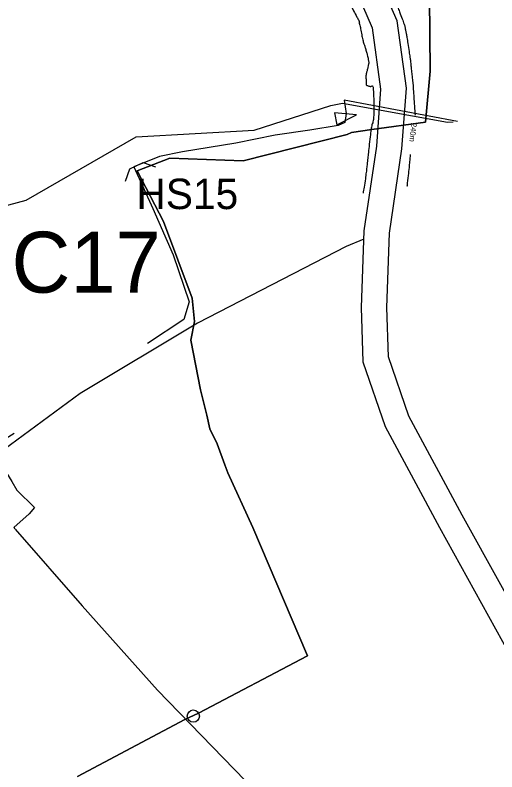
# Model space of a CAD drawing. Extents: x -478495 to -472450, y -1118050 to -1113745.
# Drawn here: x -476752.6 to -476594.3, y -1115728.8 to -1115480.3 of the extents above; entities that cross this region are included whole.
import ezdxf

# ---------------------------------------------------------------- set-up
doc = ezdxf.new("R2010")
doc.units = 0
for name, color, linetype in [('cesty', 7, 'Continuous'), ('el vedeni _VN', 7, 'Continuous'), ('el vedeni_NN', 7, 'Continuous'), ('hospodářské sjezdy', 7, 'Continuous'), ('ObPÚ', 7, 'Continuous'), ('vodní plochy', 7, 'Continuous'), ('Vrstevnice_hlavni', 7, 'Continuous'), ('Vrstevnice_popis', 7, 'Continuous')]:
    doc.layers.add(name, color=color, linetype=linetype)

msp = doc.modelspace()

# ---------------------------------------------------------------- linework, layer by layer
at = {"layer": 'cesty'}
msp.add_line((-476647.67265629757, -1115512.3904582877), (-476646.9333437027, -1115516.321541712), dxfattribs=at)
msp.add_lwpolyline([(-476646.9333437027, -1115516.321541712), (-476640.4761246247, -1115513.0720804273), (-476647.67265629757, -1115512.3904582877)], dxfattribs=at)
msp.add_circle((-476694.08534708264, -1115710.4661019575), 2, dxfattribs=at)
at = {"layer": 'el vedeni _VN'}
for points in [[(-476960.505, -1115493.233), (-476958.229, -1115494.183), (-476899.623, -1115513.536), (-476849.434, -1115530.972), (-476828.522, -1115538.992), (-476787.371, -1115551.3360000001), (-476749.039, -1115541.109), (-476712.836, -1115520.229), (-476674.07800000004, -1115518.099), (-476648.949, -1115510.002), (-476645.0645000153, -1115509.1674999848), (-476610.607, -1115515.4054999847), (-476608.699, -1115515.3360000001)], [(-476607.29025000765, -1115515.24), (-476644.57, -1115508.27), (-476643.83, -1115512.6285000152), (-476644.33, -1115515.5485000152), (-476646.46, -1115516.5485000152), (-476655.81, -1115518.0985000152), (-476667.18, -1115519.7085000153), (-476680.17, -1115522.3285000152), (-476697.65, -1115525.2285000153), (-476705.17, -1115526.7285000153), (-476713.65, -1115530.1385000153), (-476707.36, -1115543.8085000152), (-476700.72000000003, -1115559.0085000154), (-476695.5, -1115574.4385000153), (-476697.2, -1115580.2585000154), (-476709.1420331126, -1115588.1778778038)], [(-476752.99, -1115617.645), (-476760.59, -1115622.4385000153), (-476753.68, -1115633.3885000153), (-476752.07, -1115636.2785000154), (-476746.28, -1115641.9985000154), (-476748.07, -1115644.0885000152), (-476753.11, -1115648.49), (-476752.7125000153, -1115648.935)]]:
    msp.add_lwpolyline(points, dxfattribs=at)
at = {"layer": 'el vedeni_NN'}
msp.add_lwpolyline([(-476752.574, -1115649.0925000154), (-476730.57, -1115674.25), (-476705.81, -1115701.99), (-476648.0910886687, -1115761.4029674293)], dxfattribs=at)
at = {"layer": 'hospodářské sjezdy'}
for p, q in [((-476714.955, -1115530.759), (-476710.5445180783, -1115528.6585611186)), ((-476710.5445180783, -1115528.6585611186), (-476706.52371015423, -1115530.0823549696)), ((-476716.3837131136, -1115534.778062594), (-476714.955, -1115530.759))]:
    msp.add_line(p, q, dxfattribs=at)
at = {"layer": 'ObPÚ'}
for p, q in [((-476616.6289291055, -1115459.8410812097), (-476616.2596414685, -1115498.6901405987)), ((-476616.2596414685, -1115498.6901405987), (-476616.6289291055, -1115459.8410812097)), ((-476616.2596414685, -1115498.6901405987), (-476617.82961543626, -1115515.4656638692)), ((-476617.82961543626, -1115515.4656638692), (-476616.2596414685, -1115498.6901405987)), ((-476617.82961543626, -1115515.4656638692), (-476635.39030686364, -1115517.8817167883)), ((-476635.39030686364, -1115517.8817167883), (-476617.82961543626, -1115515.4656638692)), ((-476642.12939695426, -1115518.8089011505), (-476643.54326731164, -1115519.5005700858)), ((-476643.54326731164, -1115519.5005700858), (-476642.12939695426, -1115518.8089011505)), ((-476635.39030686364, -1115517.8817167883), (-476642.12939695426, -1115518.8089011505)), ((-476642.12939695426, -1115518.8089011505), (-476635.39030686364, -1115517.8817167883)), ((-476643.54326731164, -1115519.5005700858), (-476677.6648575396, -1115528.1907129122)), ((-476677.6648575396, -1115528.1907129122), (-476643.54326731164, -1115519.5005700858)), ((-476701.7930954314, -1115527.2491543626), (-476712.5505217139, -1115531.3951539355)), ((-476712.5505217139, -1115531.3951539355), (-476701.7930954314, -1115527.2491543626)), ((-476677.6648575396, -1115528.1907129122), (-476701.7930954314, -1115527.2491543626)), ((-476701.7930954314, -1115527.2491543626), (-476677.6648575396, -1115528.1907129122)), ((-476712.5505217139, -1115531.3951539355), (-476703.85432935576, -1115548.1069670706)), ((-476703.85432935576, -1115548.1069670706), (-476712.5505217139, -1115531.3951539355)), ((-476703.85432935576, -1115548.1069670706), (-476694.48336744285, -1115573.2811395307)), ((-476694.48336744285, -1115573.2811395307), (-476703.85432935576, -1115548.1069670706)), ((-476694.48336744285, -1115573.2811395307), (-476693.73445213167, -1115580.895112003)), ((-476693.73445213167, -1115580.895112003), (-476694.48336744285, -1115573.2811395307)), ((-476693.73445213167, -1115580.895112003), (-476694.85782512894, -1115587.0112538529)), ((-476694.85782512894, -1115587.0112538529), (-476693.73445213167, -1115580.895112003)), ((-476694.85782512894, -1115587.0112538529), (-476691.7373445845, -1115603.3625718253)), ((-476691.7373445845, -1115603.3625718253), (-476694.85782512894, -1115587.0112538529)), ((-476691.7373445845, -1115603.3625718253), (-476689.64129380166, -1115611.6184031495)), ((-476689.64129380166, -1115611.6184031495), (-476691.7373445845, -1115603.3625718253)), ((-476689.64129380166, -1115611.6184031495), (-476688.68114597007, -1115616.1310980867)), ((-476688.68114597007, -1115616.1310980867), (-476689.64129380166, -1115611.6184031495)), ((-476688.68114597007, -1115616.1310980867), (-476686.2807763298, -1115621.0278521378)), ((-476686.2807763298, -1115621.0278521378), (-476688.68114597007, -1115616.1310980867)), ((-476686.2807763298, -1115621.0278521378), (-476683.7843918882, -1115627.940916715)), ((-476683.7843918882, -1115627.940916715), (-476686.2807763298, -1115621.0278521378)), ((-476683.7843918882, -1115627.940916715), (-476682.728229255, -1115630.6293306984)), ((-476682.728229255, -1115630.6293306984), (-476683.7843918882, -1115627.940916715)), ((-476682.728229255, -1115630.6293306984), (-476674.5669724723, -1115648.584095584)), ((-476674.5669724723, -1115648.584095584), (-476682.728229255, -1115630.6293306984)), ((-476674.5669724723, -1115648.584095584), (-476656.51619281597, -1115690.7345864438)), ((-476656.51619281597, -1115690.7345864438), (-476674.5669724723, -1115648.584095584)), ((-476656.51619281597, -1115690.7345864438), (-476692.42572258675, -1115709.4574696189)), ((-476692.42572258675, -1115709.4574696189), (-476656.51619281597, -1115690.7345864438)), ((-476692.42572258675, -1115709.4574696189), (-476696.8477529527, -1115711.565702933)), ((-476696.8477529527, -1115711.565702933), (-476692.42572258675, -1115709.4574696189)), ((-476696.8477529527, -1115711.565702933), (-476732.17224607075, -1115730.3519106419)), ((-476732.17224607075, -1115730.3519106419), (-476696.8477529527, -1115711.565702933))]:
    msp.add_line(p, q, dxfattribs=at)
at = {"layer": 'vodní plochy'}
for points in [[(-476580.3837979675, -1115690.288251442), (-476605.73334849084, -1115644.5441951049), (-476623.23824600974, -1115611.954845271), (-476629.94109933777, -1115592.5616732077), (-476630.45449433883, -1115576.2748581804), (-476629.5775424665, -1115551.9267831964), (-476625.531861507, -1115524.266914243), (-476624.0902282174, -1115504.3139454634), (-476627.07755504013, -1115482.1470422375), (-476632.6667913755, -1115469.3284741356)], [(-476639.9416470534, -1115473.8077512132), (-476635.30298632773, -1115484.4462328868), (-476632.5900853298, -1115504.5768102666), (-476633.9463909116, -1115523.3487982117), (-476638.01423038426, -1115551.1601625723), (-476638.91810950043, -1115576.2558571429), (-476638.3552636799, -1115594.1114381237), (-476631.01128196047, -1115615.3595683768), (-476613.1589553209, -1115648.5957365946), (-476587.8471865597, -1115694.2716145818)], [(-476638.1130688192, -1115553.9043560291), (-476643.882, -1115556.28), (-476692.746, -1115581.454), (-476731.259, -1115604.531), (-476764.657, -1115629.099), (-476802.386, -1115652.775), (-476819.266, -1115663.622), (-476873.466, -1115698.453), (-476876.962, -1115700.938), (-476893.934, -1115713.636)]]:
    msp.add_lwpolyline(points, dxfattribs=at)
at = {"layer": 'Vrstevnice_hlavni'}
for points in [[(-476675.172, -1115442.891), (-476674.626, -1115443.23), (-476674.326, -1115443.4440000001), (-476673.998, -1115443.703), (-476673.643, -1115444.006), (-476672.012, -1115445.487), (-476669.106, -1115448.147), (-476664.923, -1115451.985), (-476662.048, -1115454.626), (-476660.479, -1115456.072), (-476660.217, -1115456.321), (-476659.967, -1115456.568), (-476659.729, -1115456.815), (-476659.50200000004, -1115457.0590000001), (-476658.33900000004, -1115458.137), (-476656.24, -1115460.049), (-476653.205, -1115462.795), (-476651.104, -1115464.702), (-476649.939, -1115465.77), (-476649.71, -1115466), (-476649.538, -1115466.17), (-476649.425, -1115466.28), (-476649.37, -1115466.33), (-476649.316, -1115466.382), (-476649.261, -1115466.437), (-476649.207, -1115466.495), (-476648.681, -1115467.234), (-476647.683, -1115468.656), (-476646.21400000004, -1115470.761), (-476645.234, -1115472.165), (-476644.744, -1115472.867), (-476644.743, -1115472.868), (-476644.742, -1115472.869), (-476644.74100000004, -1115472.87), (-476644.189, -1115473.878), (-476643.085, -1115475.892), (-476641.429, -1115478.913), (-476640.313, -1115480.954), (-476639.73600000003, -1115482.014), (-476639.7, -1115482.095), (-476639.658, -1115482.232), (-476639.61, -1115482.426), (-476639.555, -1115482.676), (-476639.518, -1115482.842), (-476639.5, -1115482.925), (-476639.501, -1115482.924), (-476639.378, -1115483.565), (-476639.13300000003, -1115484.8460000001), (-476638.766, -1115486.769), (-476638.40400000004, -1115488.387), (-476638.048, -1115489.699), (-476637.69800000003, -1115490.706), (-476637.354, -1115491.828), (-476637.017, -1115493.063), (-476636.686, -1115494.413), (-476636.484, -1115495.376), (-476636.411, -1115495.954), (-476636.467, -1115496.145), (-476636.54600000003, -1115496.4980000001), (-476636.648, -1115497.014), (-476636.772, -1115497.691), (-476636.911, -1115498.298), (-476637.064, -1115498.8360000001), (-476637.232, -1115499.305), (-476637.332, -1115499.8800000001), (-476637.364, -1115500.562), (-476637.32800000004, -1115501.351), (-476637.305, -1115501.916), (-476637.295, -1115502.2550000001), (-476637.299, -1115502.369), (-476637.302, -1115502.476), (-476637.305, -1115502.575), (-476637.308, -1115502.666), (-476637.314, -1115502.785), (-476637.32300000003, -1115502.931), (-476637.335, -1115503.105), (-476637.185, -1115503.279), (-476636.871, -1115503.453), (-476636.395, -1115503.627), (-476635.985, -1115503.7), (-476635.641, -1115503.673), (-476635.364, -1115503.545), (-476635.163, -1115503.629), (-476635.036, -1115503.926), (-476634.985, -1115504.435), (-476634.924, -1115505.348), (-476634.853, -1115506.665), (-476634.773, -1115508.386), (-476634.73, -1115509.857), (-476634.72500000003, -1115511.078), (-476634.757, -1115512.048), (-476634.794, -1115512.909), (-476634.835, -1115513.661), (-476634.88, -1115514.304), (-476634.98600000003, -1115514.959), (-476635.152, -1115515.626)], [(-476649.162, -1115445.383), (-476649.04000000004, -1115445.49), (-476648.941, -1115445.572), (-476648.865, -1115445.628), (-476648.813, -1115445.658), (-476648.733, -1115445.739), (-476648.624, -1115445.87), (-476648.485, -1115446.051), (-476647.64, -1115446.857), (-476646.086, -1115448.29), (-476643.825, -1115450.347), (-476642.282, -1115451.76), (-476641.45900000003, -1115452.527), (-476641.355, -1115452.649), (-476640.97500000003, -1115453.3090000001), (-476640.32, -1115454.508), (-476639.39, -1115456.245), (-476638.72500000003, -1115457.487), (-476638.325, -1115458.232), (-476638.189, -1115458.482), (-476638.072, -1115458.678), (-476637.972, -1115458.818), (-476637.89, -1115458.904), (-476637.818, -1115458.9980000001), (-476637.755, -1115459.099), (-476637.701, -1115459.209), (-476637.598, -1115459.369), (-476637.444, -1115459.58), (-476637.24100000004, -1115459.842), (-476636.68700000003, -1115460.676), (-476635.784, -1115462.084), (-476634.52900000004, -1115464.064), (-476633.647, -1115465.448), (-476633.135, -1115466.236), (-476632.994, -1115466.428), (-476632.881, -1115466.609), (-476632.795, -1115466.779), (-476632.737, -1115466.94), (-476632.656, -1115467.089), (-476632.553, -1115467.2280000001), (-476632.427, -1115467.356), (-476631.9, -1115468.24), (-476630.973, -1115469.8800000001), (-476629.645, -1115472.275), (-476628.72500000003, -1115473.931), (-476628.212, -1115474.8460000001), (-476628.107, -1115475.022), (-476628.006, -1115475.185), (-476627.909, -1115475.337), (-476627.816, -1115475.477), (-476627.693, -1115475.718), (-476627.539, -1115476.06), (-476627.355, -1115476.503), (-476626.941, -1115477.57), (-476626.298, -1115479.261), (-476625.42600000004, -1115481.577), (-476624.826, -1115483.283), (-476624.499, -1115484.379), (-476624.444, -1115484.865), (-476624.364, -1115485.358), (-476624.256, -1115485.859), (-476624.123, -1115486.367), (-476623.9, -1115487.607), (-476623.587, -1115489.58), (-476623.185, -1115492.284), (-476622.903, -1115494.208), (-476622.739, -1115495.352), (-476622.695, -1115495.716), (-476622.601, -1115496.605), (-476622.457, -1115498.019), (-476622.264, -1115499.957), (-476622.11100000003, -1115501.4170000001), (-476622, -1115502.399), (-476621.93, -1115502.903), (-476621.882, -1115503.325), (-476621.857, -1115503.666), (-476621.854, -1115503.924), (-476621.783, -1115505.089), (-476621.64400000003, -1115507.16), (-476621.43700000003, -1115510.137), (-476621.299, -1115512.128), (-476621.23, -1115513.132), (-476621.229, -1115513.166)], [(-476635.152, -1115515.626), (-476635.379, -1115516.305), (-476635.65400000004, -1115517.842), (-476635.977, -1115520.236), (-476636.347, -1115523.487), (-476636.628, -1115525.999), (-476636.819, -1115527.773), (-476636.92100000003, -1115528.807), (-476637.07800000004, -1115530.196), (-476637.292, -1115531.938), (-476637.56200000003, -1115534.035), (-476638.001, -1115536.851), (-476638.3335432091, -1115538.8126863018)], [(-476623.77733585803, -1115536.4726767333), (-476623.75800000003, -1115536.31), (-476623.38, -1115532.975), (-476623.098, -1115530.352), (-476622.914, -1115528.44), (-476622.74, -1115526.038)]]:
    msp.add_spline(points, degree=3, dxfattribs=at)

# ---------------------------------------------------------------- texts
at = {"layer": 'cesty'}
msp.add_text('C17', height=19.99999999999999, rotation=359.99999385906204, dxfattribs=at).set_placement((-476753.814944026, -1115571.4323601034))
at = {"layer": 'hospodářské sjezdy'}
msp.add_text('HS15', height=9.999999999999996, rotation=359.99999385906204, dxfattribs=at).set_placement((-476712.78537200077, -1115544.0007060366))
at = {"layer": 'Vrstevnice_popis'}
msp.add_text(' 240m ', height=1.7999999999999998, rotation=263.3036508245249, dxfattribs=at).set_placement((-476622.343, -1115514.938))

doc.saveas('drawing.dxf')
